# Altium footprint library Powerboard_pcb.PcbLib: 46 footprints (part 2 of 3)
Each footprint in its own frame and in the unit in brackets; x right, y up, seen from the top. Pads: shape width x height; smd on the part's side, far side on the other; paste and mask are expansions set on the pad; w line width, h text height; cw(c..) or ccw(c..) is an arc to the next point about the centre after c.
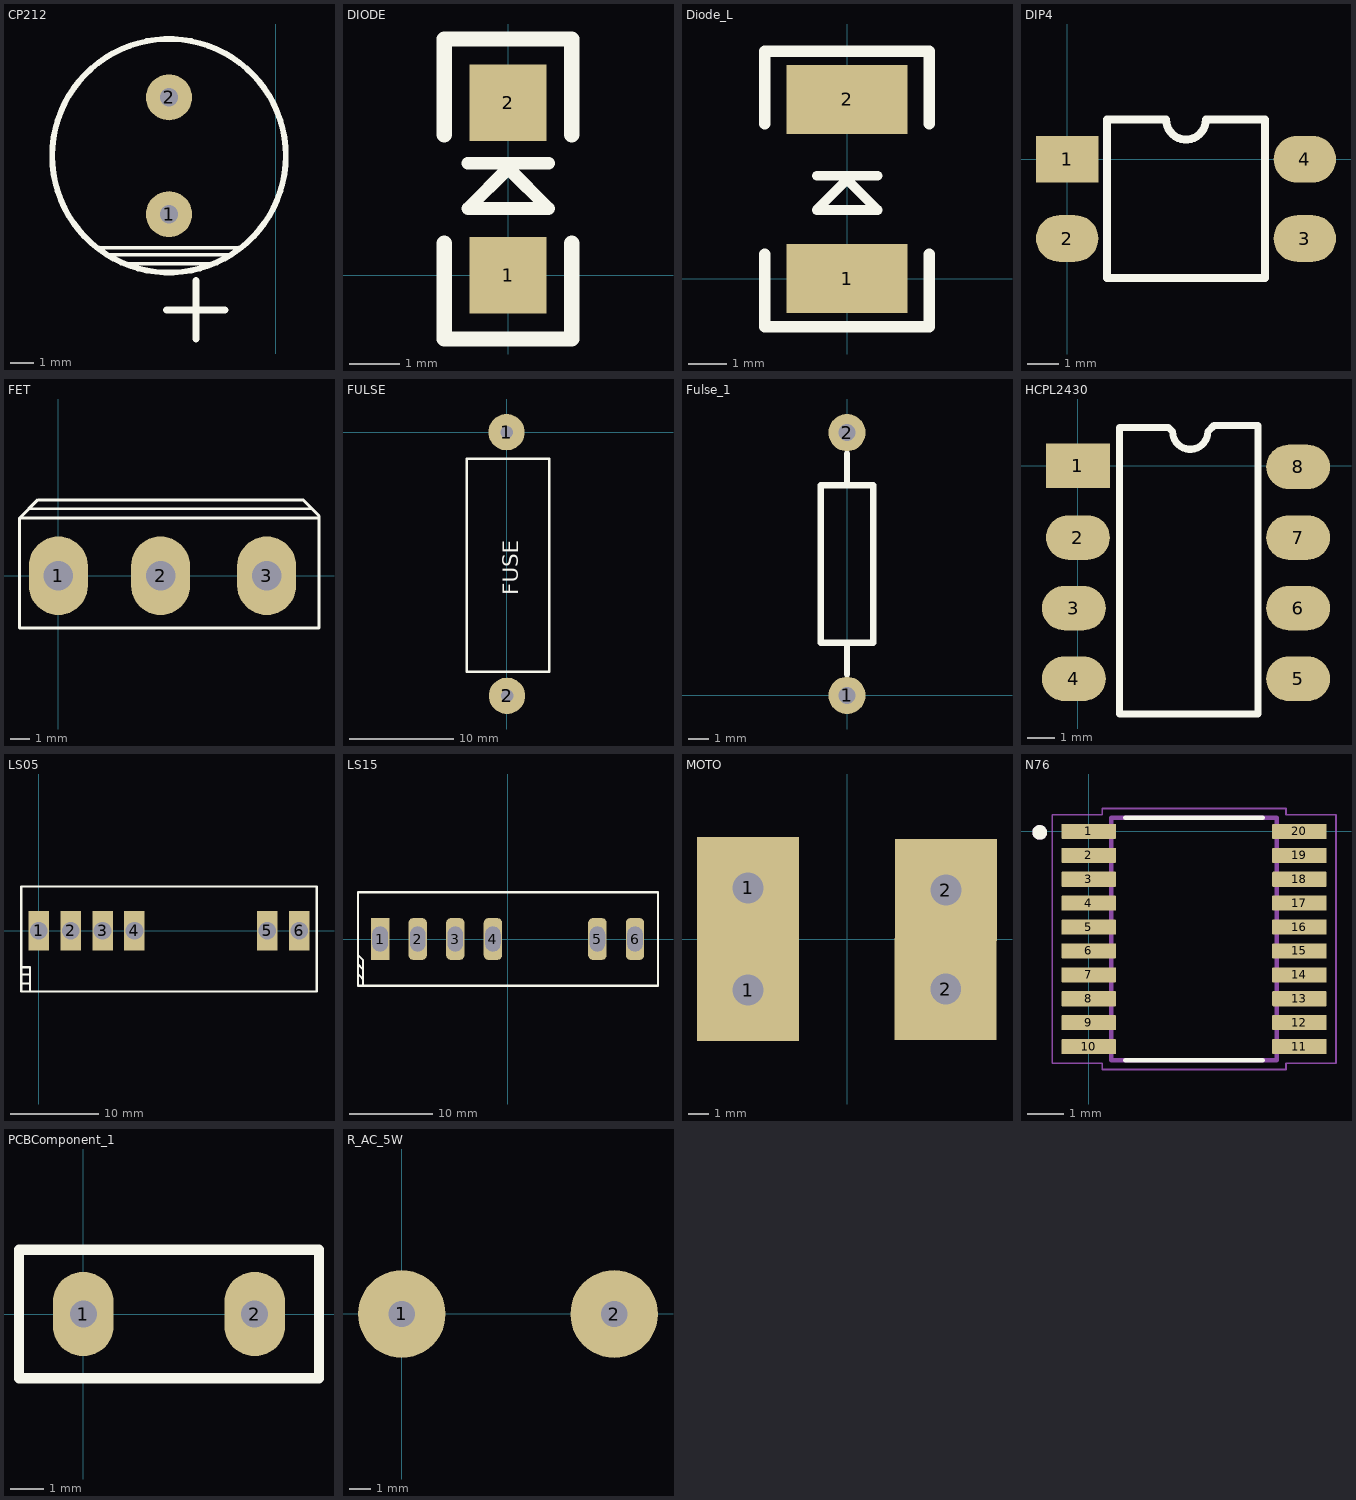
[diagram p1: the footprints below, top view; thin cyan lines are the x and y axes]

## CP212 [mm]
pads (2):
  round 2 hole 0.8: 1(-4.647,30.296) 2(-4.647,35.376)
Top Overlay:
  circle w0.254: c-4.647,32.836 r5.08
  lines w0.15: -7.798,28.829 -1.575,28.829 -1.88,28.524 -7.214,28.524 ; -6.71,28.194 -6.66,28.143 -2.819,28.143
  lines w0.305: -4.75,26.137 -2.21,26.137 ; -3.48,24.867 -3.48,27.407

## DIODE [mil]
pads (2):
  rect 60x60 smd: 1(0,0) 2(0,135)
Top Overlay:
  lines w10: -31.32,87.66 31.67,87.66 ; -31.32,52.23 0.17,83.73 31.67,52.23 -31.32,52.23
  lines w12: -50,25 -50,-50 50,-50 50,25 ; -50,110 -50,185 50,185 50,110

## Diode_L [mm]
pads (2):
  rect 3.175x1.8 smd: 1(0,0) 2(0,4.699)
Top Layer:
  lines w0.254: -0.21,4.399 -0.198,4.387
Top Overlay:
  lines w0.254: -0.796,2.699 0.804,2.699 ; 0.004,2.599 -0.796,1.799 0.804,1.799 0.004,2.599 ; 0.004,2.599 0.004,2.599
  lines w0.305: -2.159,0.635 -2.159,-1.27 2.159,-1.27 2.159,0.635 ; -2.159,4.064 -2.159,5.969 2.159,5.969 2.159,4.064

## DIP4 [mm]
pads (4):
  rect 2x1.5 smd: 1(0,0)
  oval 2x1.5 smd: 2(0,-2.54) 3(7.62,-2.54) 4(7.62,0)
Top Overlay:
  lines w0.254: 1.27,-3.81 1.27,1.27 3.175,1.27 ccw(c3.81,1.27) 4.445,1.27 6.35,1.27 6.35,-3.81 1.27,-3.81

## FET [mm]
pads (3):
  oval 3x4 hole 1.5: 1(0,0) 2(5.2,0) 3(10.6,0)
Top Overlay:
  lines w0.15: -1.981,2.946 13.259,2.946 ; -1.511,3.391 12.852,3.427 ; -1.981,-2.667 -1.981,2.921 -1.041,3.861 12.446,3.861 13.259,3.048 13.259,-2.667 -1.981,-2.667

## FULSE [mm]
pads (2):
  round 3.5 hole 1.2: 1(0,0) 2(0.048,-25.347)
Top Layer:
  lines w0.254: -0.006,-25.347 0.048,-25.347
Top Overlay:
  lines w0.254: -3.835,-23.047 4.115,-23.047 4.115,-2.547 -3.835,-2.547 -3.835,-23.047
  text "FUSE" at 1.145,-15.674 h1.5

## Fulse_1 [mm]
pads (2):
  round 1.8 hole 0.813: 1(0,0) 2(0,12.7)
Top Overlay:
  lines w0.305: 0,1.016 0,2.54 ; 0,10.16 0,11.684 ; -1.27,2.54 1.27,2.54 1.27,10.16 -1.27,10.16 -1.27,2.54

## HCPL2430 [mm]
pads (8):
  rect 2.3x1.6 smd: 1(0,0)
  oval 2.3x1.6 smd: 2(0,-2.591) 3(-0.15,-5.131) 4(-0.15,-7.671) 5(7.925,-7.671) 6(7.925,-5.131) 7(7.925,-2.591) 8(7.925,-0.051)
Top Overlay:
  lines w0.254: 1.499,-8.941 1.499,1.372 3.251,1.372 3.404,1.219 ccw(c4.039,1.219) 4.674,1.219 4.902,1.448 6.477,1.448 6.477,-8.941 1.499,-8.941

## LS05 [mm]
pads (6):
  rect 2.3x4.5 hole 2: 1(0,0) 2(3.6,0) 3(7.2,0) 4(10.8,0) 5(25.82,0) 6(29.42,0)
Top Overlay:
  lines w0.254: -1.983,-5.972 -1.041,-5.972 ; -1.956,-4.953 -1.016,-4.956 ; -1.956,-4.144 -1.016,-4.144 -1.016,-6.706 ; -2.007,-6.883 31.42,-6.883 31.42,5 -2.007,5 -2.007,-6.883

## LS15 [mm]
pads (6):
  rect 2.2x5 hole 3 slot 1.85 at 0 deg: 1(-15.25,0)
  rrect50% 2.2x5 hole 3 slot 1.82 at 0 deg: 2(-10.75,0) 3(-6.25,0) 4(-1.75,0) 5(10.75,0) 6(15.25,0)
Top Overlay:
  lines w0.254: -17.891,-3.048 -17.39,-3.549 ; -17.866,-1.956 -17.282,-2.54 -17.282,-5.588 ; -17.853,-4.229 -17.39,-4.692 ; -17.892,-5.588 -17.892,5.588 18,5.588 18,-5.588 -17.892,-5.588

## MOTO [mm]
pads (4):
  rect 5x5 hole 1.5: 1(-4.85,-2.5) 1(-4.85,2.5) 2(4.836,-2.45) 2(4.85,2.4)

## N76 [mm]
pads (20):
  rrect10% 1.48x0.41 smd: 1(0,0) 2(0,-0.65) 3(0,-1.3) 4(0,-1.95) 5(0,-2.6) 6(0,-3.25) 7(0,-3.9) 8(0,-4.55) 9(0,-5.2) 10(0,-5.85) 11(5.73,-5.85) 12(5.73,-5.2) 13(5.73,-4.55) 14(5.73,-3.9) 15(5.73,-3.25) 16(5.73,-2.6) 17(5.73,-1.95) 18(5.73,-1.3) 19(5.73,-0.65) 20(5.73,0)
Top Overlay:
  circle w0.2: c-1.335,-0.025 r0.1
  lines w0.127: 0.996,-6.225 4.734,-6.225 ; 0.996,0.375 4.734,0.375
Mechanical 13:
  circle w0.2: c-1.335,-0.025 r0.1
  lines w0.127: 0.615,-6.225 5.115,-6.225 5.115,0.375 0.615,0.375 0.615,-6.225
Mechanical 15:
  lines w0.05: -0.995,-6.305 -0.995,0.455 0.365,0.455 0.365,0.625 5.365,0.625 5.365,0.455 6.725,0.455 6.725,-6.305 5.365,-6.305 5.365,-6.475 0.365,-6.475 0.365,-6.305 -0.995,-6.305

## PCBComponent_1 [mm]
pads (2):
  oval 1.8x2.5 hole 0.8: 1(0,0) 2(5.08,0)
Top Overlay:
  lines w0.305: -1.905,-1.905 6.985,-1.905 6.985,1.905 -1.905,1.905 -1.905,-1.905

## PCBComponent_1 - duplicate [mm]

## PCBComponent_1 - duplicate1 [mm]

## R_AC_5W [mm]
pads (2):
  round 4 hole 1.2: 1(0,0) 2(9.7,0)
